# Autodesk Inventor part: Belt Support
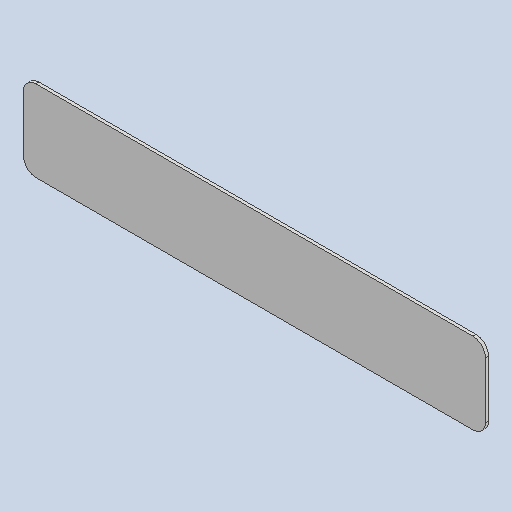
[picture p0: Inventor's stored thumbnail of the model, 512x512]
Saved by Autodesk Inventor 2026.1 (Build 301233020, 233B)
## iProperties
Created: 2026-10
Part Number: Belt Support
Material: Generic
Document SubType Name: Modeling
Designer: hp
Density: 1 g/cm^3
Appearance: Default
Author: hp
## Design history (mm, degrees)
sketch "Sketch1"
  geometry: L1 (0, 0)-(740, 0); L2 (740, 0)-(740, 130); L3 (740, 130)-(0, 130); L4 (0, 130)-(0, 0)
  constraints: 8 end point, 2 parallel, 1 horizontal, 1 perpendicular
  dimensions: "d0" = 740 distance of L3.end L2.end; "d1" = 130 distance of L2.end L1.end
extrude "Extrusion1" new body sketch "Sketch1" distance "d2" = 5; taper "d3" = 0 deg
fillet "Fillet1" dims "d4" = 20
body "Solid1"
